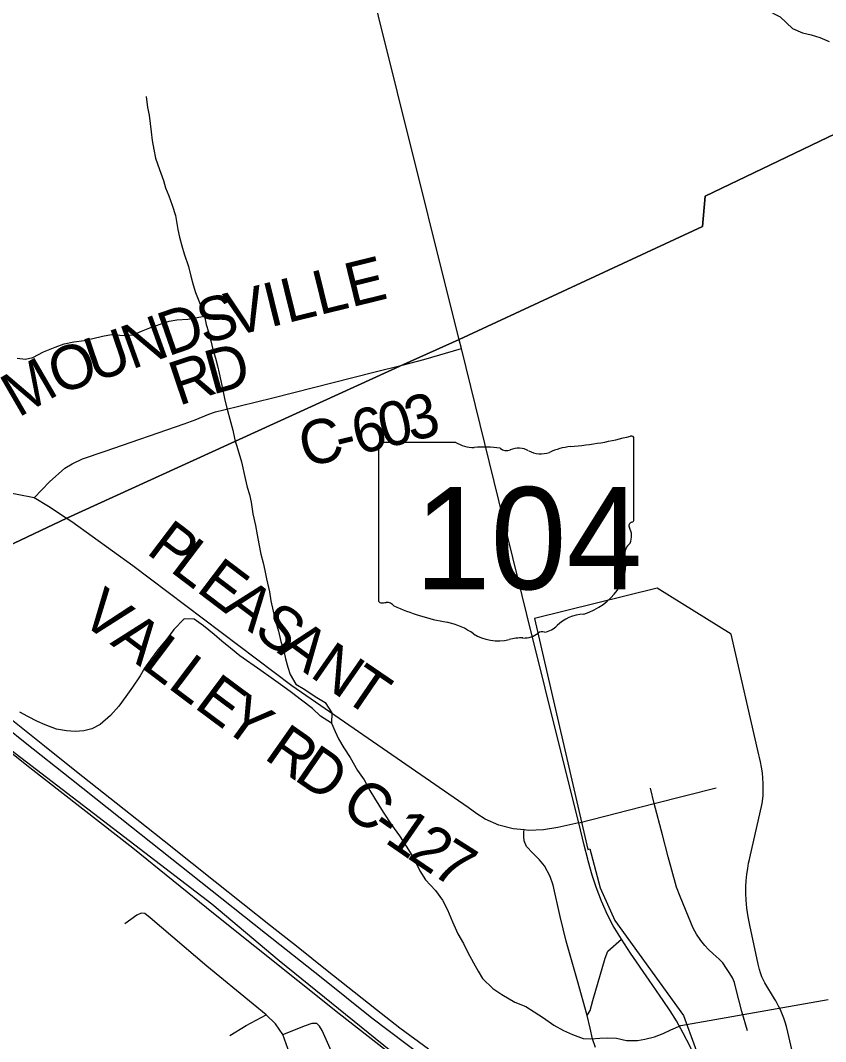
# Model space of a CAD drawing. Extents: x 0 to 34, y 0 to 22.
# Drawn here: x 3.32 to 4.36, y 15.912 to 17.231 of the extents above; entities that cross this region are included whole.
import ezdxf

# ---------------------------------------------------------------- set-up
doc = ezdxf.new("R2010")
doc.units = 0
for name, color, linetype in [('GM_X_City_Street', 7, 'Continuous'), ('GM_X_Corporation', 7, 'Continuous'), ('GM_X_County_Road', 7, 'Continuous'), ('GM_X_County_Road_Text', 7, 'Continuous'), ('GM_X_Major_River', 7, 'Continuous'), ('GM_X_Minor_River', 7, 'Continuous'), ('GM_X_Rail_Line', 7, 'Continuous'), ('GM_X_State_Location', 7, 'Continuous'), ('GM_X_State_Route', 7, 'Continuous'), ('GM_X_State_Shield', 7, 'Continuous'), ('GM_X_Township_Road', 7, 'Continuous'), ('GM_X_US_Route', 7, 'Continuous'), ('SH_Data', 7, 'Continuous')]:
    doc.layers.add(name, color=color, linetype=linetype)

msp = doc.modelspace()

# ---------------------------------------------------------------- linework, layer by layer
at = {"layer": 'GM_X_City_Street'}
for points in [[(4.0409, 16.1947), (4.1384, 16.2197), (4.2183, 16.2402)], [(4.2588, 15.9262), (4.2514, 15.9511), (4.2438, 15.9812), (4.2419, 15.9886), (4.2394, 15.9948), (4.2362, 16.0003), (4.2318, 16.0069), (4.2268, 16.0139), (4.2222, 16.019), (4.2145, 16.0259), (4.2085, 16.0315), (4.2038, 16.0365), (4.1986, 16.0429), (4.1932, 16.051), (4.1887, 16.0588), (4.1825, 16.0735), (4.1721, 16.0996), (4.1673, 16.112), (4.1565, 16.1509), (4.1492, 16.1794), (4.1384, 16.2197), (4.1338, 16.2396)]]:
    msp.add_lwpolyline(points, dxfattribs=at)
at = {"layer": 'GM_X_Corporation'}
for points in [[(2.1, 20.9), (2.1, 15.9991), (2.5081, 16.1858), (2.5106, 16.1869), (3.1538, 16.4811), (3.1598, 16.4838), (3.1648, 16.4862), (3.1819, 16.4943), (3.1836, 16.4951), (3.3801, 16.588), (3.8146, 16.7867), (3.8864, 16.8187), (4.2007, 16.9645), (4.2041, 17.0039), (4.5514, 17.1703), (4.4931, 17.1874), (4.4442, 17.208), (4.4091, 17.232)], [(4.8947, 17.2375), (4.8723, 17.2265), (4.8654, 17.2194), (4.8479, 17.2074), (4.8289, 17.1916), (4.7856, 17.1626), (4.7444, 17.154), (4.6218, 17.1548), (4.5797, 17.1651), (4.5514, 17.1703), (4.2041, 17.0039), (4.2007, 16.9645), (3.8864, 16.8187), (3.8146, 16.7867), (3.3801, 16.588), (3.1836, 16.4951)], [(4.3578, 15.722), (4.311, 15.9248), (4.3093, 15.9318), (4.3075, 15.9376), (4.3058, 15.9427), (4.3041, 15.947), (4.3024, 15.9511), (4.3006, 15.955), (4.299, 15.9581), (4.2972, 15.9616), (4.2953, 15.9649), (4.2938, 15.9675), (4.2813, 15.9883), (4.2791, 15.9925), (4.2775, 15.9962), (4.2756, 16.0011), (4.2742, 16.0056), (4.2733, 16.009), (4.2725, 16.0123), (4.2618, 16.0629), (4.2596, 16.0736), (4.2579, 16.0847), (4.257, 16.0949), (4.2567, 16.1038), (4.2568, 16.1125), (4.2572, 16.1201), (4.258, 16.1286), (4.2591, 16.136), (4.2603, 16.1428), (4.2613, 16.1476), (4.2618, 16.1496), (4.278, 16.2198), (4.2789, 16.2295), (4.2792, 16.2381), (4.2791, 16.2456), (4.2788, 16.2526), (4.2781, 16.2593), (4.2771, 16.2666), (4.2758, 16.2735), (4.2745, 16.2791), (4.2736, 16.2827), (4.2377, 16.4382), (4.1421, 16.498), (3.9837, 16.4585), (4.0525, 16.1606), (4.0552, 16.1613), (4.0687, 16.1108), (4.0875, 16.0686), (4.1764, 15.9463), (4.2064, 15.8637)], [(3.9424, 15.7834), (3.6542, 16.0168), (3.5673, 16.0897), (3.2872, 16.3043)]]:
    msp.add_lwpolyline(points, dxfattribs=at)
at = {"layer": 'GM_X_County_Road'}
for points in [[(3.3378, 16.6142), (3.3577, 16.6352), (3.3776, 16.6525), (3.3868, 16.6584), (3.4001, 16.6647), (3.4293, 16.6747), (3.5313, 16.7098), (3.5457, 16.7152), (3.5635, 16.7225), (3.5719, 16.7254), (3.5827, 16.7281), (3.6459, 16.7437), (3.7765, 16.7766), (3.8148, 16.7862), (3.8411, 16.7931), (3.8895, 16.807)], [(3.3378, 16.6142), (3.3161, 16.6186), (3.2542, 16.6304), (3.1999, 16.6441), (3.1865, 16.6487)], [(3.3803, 16.5875), (3.3562, 16.6033), (3.3378, 16.6142)], [(3.898, 16.2145), (3.6707, 16.3719), (3.4653, 16.5268), (3.3864, 16.5835), (3.3803, 16.5875)], [(4.0409, 16.1947), (4.0141, 16.189), (3.9954, 16.1857), (3.9759, 16.1851), (3.9707, 16.1857), (3.9565, 16.1872), (3.9379, 16.192), (3.9203, 16.1995), (3.9095, 16.2066), (3.898, 16.2145)], [(4.0624, 15.9049), (4.0587, 15.916), (4.0557, 15.9297), (4.0519, 15.9459), (4.0395, 15.9909), (4.0247, 16.0422), (4.0171, 16.0739), (4.0081, 16.1144), (4.0039, 16.1257), (3.9967, 16.1395), (3.9904, 16.147), (3.9816, 16.1555), (3.9735, 16.1644), (3.9707, 16.1717), (3.9699, 16.1771), (3.9702, 16.1831), (3.9707, 16.1857)], [(4.0519, 15.9459), (4.0558, 15.9527), (4.0593, 15.9653), (4.0749, 16.0201), (4.0784, 16.0292), (4.0961, 16.0445)]]:
    msp.add_lwpolyline(points, dxfattribs=at)
at = {"layer": 'GM_X_Major_River'}
for points in [[(4.1883, 17.2806), (4.2305, 17.2646), (4.2479, 17.2569), (4.2661, 17.2522), (4.2835, 17.2444), (4.3009, 17.2352), (4.3171, 17.2202)], [(4.3171, 17.2202), (4.3299, 17.2149), (4.3409, 17.2122), (4.3523, 17.2088), (4.3644, 17.2035)]]:
    msp.add_lwpolyline(points, dxfattribs=at)
at = {"layer": 'GM_X_Minor_River'}
for points in [[(3.4823, 17.1323), (3.4841, 17.1183), (3.4862, 17.1084), (3.489, 17.0871), (3.4904, 17.0757), (3.4922, 17.0639), (3.4947, 17.0529), (3.4995, 17.0381), (3.5047, 17.024), (3.5076, 17.0145), (3.5116, 17.0042), (3.5161, 16.9924), (3.5205, 16.9787), (3.5233, 16.9608), (3.5255, 16.9509), (3.5284, 16.9399), (3.5317, 16.9292), (3.5372, 16.9129), (3.5401, 16.9007), (3.543, 16.8893), (3.5463, 16.8794), (3.553, 16.8623), (3.5577, 16.8489), (3.5599, 16.8383), (3.5628, 16.8288), (3.5661, 16.817), (3.5686, 16.806), (3.5719, 16.7949), (3.5745, 16.785), (3.5767, 16.7752), (3.5788, 16.7653), (3.5813, 16.7535), (3.5842, 16.7406), (3.5875, 16.7272), (3.5904, 16.7158), (3.5944, 16.7018), (3.597, 16.6892), (3.6006, 16.677), (3.6054, 16.6607), (3.6104, 16.6394), (3.613, 16.628), (3.6159, 16.6185), (3.6181, 16.609), (3.6202, 16.5938), (3.6234, 16.5789), (3.6256, 16.5668), (3.6281, 16.555), (3.6306, 16.5417), (3.6335, 16.5306), (3.6357, 16.5208), (3.6379, 16.5097), (3.6419, 16.493), (3.6436, 16.4816), (3.6465, 16.4683), (3.6491, 16.4569), (3.6531, 16.4424), (3.6563, 16.4291), (3.66, 16.4169), (3.6622, 16.4067), (3.6655, 16.396), (3.6684, 16.3865), (3.6758, 16.3739), (3.6871, 16.367), (3.7007, 16.3581), (3.7134, 16.3501), (3.722, 16.3367), (3.7219, 16.3234), (3.7263, 16.3127), (3.7308, 16.3032), (3.7378, 16.2918), (3.7457, 16.2792), (3.7553, 16.2624), (3.7639, 16.2502), (3.7713, 16.2364), (3.7773, 16.2265), (3.7885, 16.2086), (3.7993, 16.1922), (3.8097, 16.178), (3.8183, 16.1647), (3.8276, 16.1498), (3.8358, 16.133), (3.8432, 16.1212), (3.8559, 16.1074), (3.8649, 16.0948), (3.8716, 16.0826), (3.8779, 16.067), (3.8849, 16.0514), (3.8923, 16.0392), (3.8979, 16.0273), (3.905, 16.014), (3.9113, 16.0033), (3.9169, 15.9938), (3.93, 15.9811), (3.9416, 15.9734), (3.9586, 15.9634), (3.9725, 15.9576), (3.9834, 15.951), (3.9955, 15.943), (4.0086, 15.9337), (4.0211, 15.9268), (4.0331, 15.9214)], [(3.4135, 16.8203), (3.426, 16.8232), (3.4378, 16.8254), (3.4541, 16.8241), (3.4658, 16.8247), (3.4765, 16.8296), (3.4871, 16.834), (3.502, 16.8392), (3.5122, 16.8425), (3.5221, 16.8443), (3.5361, 16.845), (3.5577, 16.8489)], [(3.3159, 16.7946), (3.3265, 16.7934), (3.336, 16.7956), (3.3497, 16.803), (3.3649, 16.809), (3.3767, 16.8134), (3.3892, 16.816), (3.4025, 16.8174), (3.4135, 16.8203)], [(3.7219, 16.3234), (3.7076, 16.3327), (3.6971, 16.3426), (3.6828, 16.3534), (3.67, 16.363), (3.6588, 16.3714), (3.6437, 16.3822), (3.6306, 16.3914), (3.6035, 16.4106), (3.5915, 16.4202), (3.5802, 16.4294), (3.5701, 16.4379), (3.5566, 16.449), (3.5445, 16.4579), (3.5317, 16.458), (3.5183, 16.4444), (3.5087, 16.4316), (3.4975, 16.4181), (3.4879, 16.4053), (3.4802, 16.3943), (3.4745, 16.3845), (3.4648, 16.3698), (3.4564, 16.3581), (3.4472, 16.3453), (3.4364, 16.3332), (3.4231, 16.3216), (3.4124, 16.316), (3.4018, 16.3135), (3.3908, 16.3128), (3.3794, 16.3137), (3.3666, 16.3157), (3.3522, 16.3215), (3.342, 16.3258), (3.3296, 16.3323), (3.3195, 16.3377)], [(4.0331, 15.9214), (4.0467, 15.9163), (4.0565, 15.9158), (4.0683, 15.9169), (4.0782, 15.9172), (4.0899, 15.9167), (4.1027, 15.9139), (4.1167, 15.9138), (4.1262, 15.9156), (4.1388, 15.9185), (4.1498, 15.9229), (4.1597, 15.9274), (4.1726, 15.933), (4.363, 15.9666)]]:
    msp.add_lwpolyline(points, dxfattribs=at)
at = {"layer": 'GM_X_Rail_Line'}
msp.add_lwpolyline([(2.1, 16.8228), (2.1358, 16.8282), (2.1875, 16.8321), (2.2635, 16.8323), (2.3249, 16.8251), (2.3996, 16.8184), (2.4546, 16.8097), (2.5216, 16.7954), (2.5976, 16.772), (2.6544, 16.7517), (2.7256, 16.7157), (2.7928, 16.6809), (2.8517, 16.6435), (2.9129, 16.5996), (3.0775, 16.4694), (3.2031, 16.3691), (3.3322, 16.2662), (3.4651, 16.1627), (3.5695, 16.0783), (3.7315, 15.9489), (3.9997, 15.7391), (4.1856, 15.5884)], dxfattribs=at)
at = {"layer": 'GM_X_State_Route'}
for points in [[(3.807, 17.1378), (3.7825, 17.2362), (3.754, 17.353)], [(3.8895, 16.807), (3.8867, 16.8182), (3.807, 17.1378)], [(4.0212, 16.2738), (3.974, 16.4637), (3.8895, 16.807)], [(4.0531, 16.1458), (4.0526, 16.1478), (4.0478, 16.1658), (4.0409, 16.1947), (4.0212, 16.2738)], [(4.1499, 15.9655), (4.1462, 15.971), (4.1317, 15.9917), (4.1078, 16.0264), (4.0961, 16.0445), (4.0856, 16.062), (4.0783, 16.0762), (4.0702, 16.0939), (4.0635, 16.1116), (4.0583, 16.1274), (4.0531, 16.1458)], [(4.2305, 15.7922), (4.2277, 15.7993), (4.2178, 15.8251), (4.1933, 15.886), (4.1847, 15.906), (4.1759, 15.9235), (4.1673, 15.9393), (4.159, 15.9522), (4.1499, 15.9655)]]:
    msp.add_lwpolyline(points, dxfattribs=at)
at = {"layer": 'GM_X_State_Shield'}
for p, q in [((4.1121, 16.5862), (4.1121, 16.6909)), ((3.7825, 16.6824), (3.7825, 16.4823)), ((3.8823, 16.6859), (3.7858, 16.6859)), ((4.1121, 16.5862), (4.1121, 16.5862))]:
    msp.add_line(p, q, dxfattribs=at)
for centre, major_axis, start_param, end_param in [((3.9947, 16.9587), (0.3495, 0), 4.814394, 5.042369), ((4.1085, 16.6913), (0.00367, 0), 6.141152, 7.989035), ((3.7863, 16.6829), (0.00382, 0), 1.712693, 3.28349), ((3.9053, 16.7091), (0.037, 0), 4.042523, 4.731795), ((3.9176, 16.5735), (0.133, 0), 1.404758, 1.657858), ((3.9478, 16.6839), (0.0107, 0), 3.836095, 5.185415), ((3.9634, 16.6608), (0.0222, 0), 0.950623, 2.079405), ((4.0393, 16.6248), (0.0703, 0), 1.699011, 2.107814), ((3.9921, 16.6925), (0.0267, 0), 4.081561, 5.145723), ((4.1082, 16.5858), (0.00393, 0), 5.05454, 6.418171), ((4.1113, 16.5785), (0.00568, 0), 1.883978, 3.671073), ((4.0751, 16.5652), (0.0341, 0), 5.934695, 6.695948), ((4.1253, 16.5424), (0.0248, 0), 2.387724, 3.262537), ((4.0143, 16.529), (0.0874, 0), 5.101752, 6.440018), ((3.7863, 16.4819), (0.00385, 0), 3.00124, 4.508301), ((3.7869, 16.5024), (0.0294, 0), 4.665946, 4.897461), ((3.7929, 16.4708), (0.0106, 0), 0.519207, 1.627899), ((3.9268, 16.6506), (0.2524, 0), 4.195997, 4.488961), ((3.8515, 16.3924), (0.079, 0), 0.823519, 1.323587), ((4.0512, 16.4261), (0.0479, 0), 1.647645, 2.488434), ((3.9695, 16.4548), (0.0267, 0), 4.691044, 5.507374), ((3.9937, 16.4354), (0.00752, 0), 1.147584, 2.315152), ((3.9905, 16.4629), (0.0282, 0), 4.937069, 5.64225), ((3.9369, 16.4698), (0.0501, 0), 4.026481, 4.996735), ((3.9659, 16.4006), (0.0412, 0), 1.495662, 1.94098)]:
    msp.add_ellipse(centre, major_axis=major_axis, ratio=0.8, start_param=start_param, end_param=end_param, dxfattribs=at)
at = {"layer": 'GM_X_Township_Road'}
for points in [[(3.7513, 15.7411), (3.7465, 15.7432), (3.7432, 15.7475), (3.7254, 15.7774), (3.7005, 15.8236), (3.6797, 15.8694), (3.6676, 15.8977), (3.6587, 15.9214), (3.6494, 15.9355), (3.6375, 15.9471), (3.6205, 15.9606), (3.5609, 16.0098), (3.4878, 16.0721), (3.4806, 16.0779), (3.476, 16.0783), (3.4702, 16.0756), (3.455, 16.0646)], [(3.5904, 15.9201), (3.6116, 15.9332), (3.6375, 15.9471)], [(3.6587, 15.9214), (3.688, 15.9334), (3.6967, 15.9361), (3.7025, 15.9361)], [(3.8216, 15.708), (3.7914, 15.7633), (3.7445, 15.8483), (3.7096, 15.9267), (3.7063, 15.9323), (3.7025, 15.9361)]]:
    msp.add_lwpolyline(points, dxfattribs=at)
at = {"layer": 'GM_X_US_Route'}
for points in [[(3.3038, 16.332), (3.3273, 16.313), (3.351, 16.2942), (3.3927, 16.2612), (3.4703, 16.1996), (3.5058, 16.1714), (3.5417, 16.1428), (3.5716, 16.1191), (3.6073, 16.0908), (3.643, 16.0625), (3.6788, 16.0342), (3.7142, 16.0059), (3.7799, 15.9538), (3.8101, 15.9304), (3.8468, 15.9031)], [(3.3015, 16.3185), (3.3261, 16.2986), (3.3859, 16.2513), (3.4634, 16.1898), (3.5529, 16.1188), (3.6365, 16.0523), (3.7083, 15.9956), (3.7739, 15.9433), (3.8407, 15.8928), (3.8734, 15.8696), (3.9099, 15.8447), (3.9477, 15.8195), (3.9679, 15.806), (4.0109, 15.7777), (4.068, 15.7402), (4.1251, 15.7023), (4.1616, 15.6785), (4.2109, 15.646), (4.3152, 15.5772), (4.4063, 15.5171), (4.4469, 15.4902), (4.4981, 15.4565), (4.5056, 15.4515)]]:
    msp.add_lwpolyline(points, dxfattribs=at)
at = {"layer": 'SH_Data'}
for p, q in [((4.1121, 16.5862), (4.1121, 16.6909)), ((3.7825, 16.6824), (3.7825, 16.4823)), ((3.8823, 16.6859), (3.7858, 16.6859)), ((4.1121, 16.5862), (4.1121, 16.5862))]:
    msp.add_line(p, q, dxfattribs=at)
for centre, major_axis, start_param, end_param in [((3.9947, 16.9587), (0.3495, 0), 4.814394, 5.042369), ((4.1085, 16.6913), (0.00367, 0), 6.141152, 7.989035), ((3.7863, 16.6829), (0.00382, 0), 1.712693, 3.28349), ((3.9053, 16.7091), (0.037, 0), 4.042523, 4.731795), ((3.9176, 16.5735), (0.133, 0), 1.404758, 1.657858), ((3.9478, 16.6839), (0.0107, 0), 3.836095, 5.185415), ((3.9634, 16.6608), (0.0222, 0), 0.950623, 2.079405), ((4.0393, 16.6248), (0.0703, 0), 1.699011, 2.107814), ((3.9921, 16.6925), (0.0267, 0), 4.081561, 5.145723), ((4.1082, 16.5858), (0.00393, 0), 5.05454, 6.418171), ((4.1113, 16.5785), (0.00568, 0), 1.883978, 3.671073), ((4.0751, 16.5652), (0.0341, 0), 5.934695, 6.695948), ((4.1253, 16.5424), (0.0248, 0), 2.387724, 3.262537), ((4.0143, 16.529), (0.0874, 0), 5.101752, 6.440018), ((3.7863, 16.4819), (0.00385, 0), 3.00124, 4.508301), ((3.7869, 16.5024), (0.0294, 0), 4.665946, 4.897461), ((3.7929, 16.4708), (0.0106, 0), 0.519207, 1.627899), ((3.9268, 16.6506), (0.2524, 0), 4.195997, 4.488961), ((3.8515, 16.3924), (0.079, 0), 0.823519, 1.323587), ((4.0512, 16.4261), (0.0479, 0), 1.647645, 2.488434), ((3.9695, 16.4548), (0.0267, 0), 4.691044, 5.507374), ((3.9937, 16.4354), (0.00752, 0), 1.147584, 2.315152), ((3.9905, 16.4629), (0.0282, 0), 4.937069, 5.64225), ((3.9369, 16.4698), (0.0501, 0), 4.026481, 4.996735), ((3.9659, 16.4006), (0.0412, 0), 1.495662, 1.94098)]:
    msp.add_ellipse(centre, major_axis=major_axis, ratio=0.8, start_param=start_param, end_param=end_param, dxfattribs=at)

# ---------------------------------------------------------------- texts
at = {"layer": 'GM_X_County_Road_Text'}
for s, rotation, p in [('E', 13.8481, (3.7472, 16.8602)), ('L', 13.8476, (3.7059, 16.8501)), ('V', 13.8454, (3.5934, 16.8223)), ('I', 13.8456, (3.642, 16.8343)), ('L', 13.8439, (3.6646, 16.8399)), ('S', 14.6367, (3.5565, 16.8127)), ('D', 19.1353, (3.5104, 16.7967)), ('N', 19.8117, (3.4636, 16.7798)), ('U', 18.7851, (3.4152, 16.7633)), ('O', 19.0593, (3.368, 16.747)), ('D', 15.4155, (3.5679, 16.7474)), ('M', 30.1259, (3.3173, 16.7173)), ('R', 18.5905, (3.5244, 16.7328)), ('3', 14.6261, (3.8246, 16.6867)), ('6', 13.7163, (3.7557, 16.6698)), ('0', 13.8662, (3.7898, 16.6782)), ('C', 13.6689, (3.6876, 16.6533)), ('-', 13.6576, (3.7329, 16.6643)), ('P', 322.8327, (3.4811, 16.5437)), ('L', 322.8339, (3.5117, 16.5205)), ('E', 322.831, (3.5455, 16.4948)), ('V', 322.9902, (3.3948, 16.4562)), ('A', 322.8335, (3.5794, 16.4692)), ('S', 322.8684, (3.6193, 16.4389)), ('A', 322.9902, (3.4348, 16.4261)), ('A', 323.7391, (3.6506, 16.4152)), ('L', 322.9895, (3.4747, 16.396)), ('N', 325.2295, (3.6922, 16.3847)), ('L', 323.0558, (3.5087, 16.3704)), ('T', 325.6761, (3.7337, 16.3559)), ('E', 323.33, (3.5429, 16.3446)), ('Y', 323.9629, (3.5775, 16.3189)), ('R', 324.9711, (3.6331, 16.2786)), ('D', 325.4955, (3.6717, 16.2515)), ('C', 325.0866, (3.7311, 16.2107)), ('-', 325.1274, (3.7694, 16.184)), ('1', 325.3106, (3.7887, 16.1706)), ('2', 325.9542, (3.8181, 16.1502)), ('7', 327.6599, (3.8486, 16.1296))]:
    msp.add_text(s, height=0.0568, rotation=rotation, dxfattribs=at).set_placement(p)
at = {"layer": 'GM_X_State_Location'}
for s in ['s', 'r']:
    msp.add_text(s, height=0.000189, dxfattribs=at).set_placement((3.9436, 16.5691))
msp.add_text('104', height=0.000189, rotation=0, dxfattribs=at).set_placement((3.8768, 16.5553))
at = {"layer": 'GM_X_State_Shield'}
msp.add_text('104', height=0.13184, dxfattribs=at).set_placement((3.8291, 16.4964))
at = {"layer": 'SH_Data'}
msp.add_text('104', height=0.13184, dxfattribs=at).set_placement((3.8291, 16.4964))

doc.saveas('drawing.dxf')
